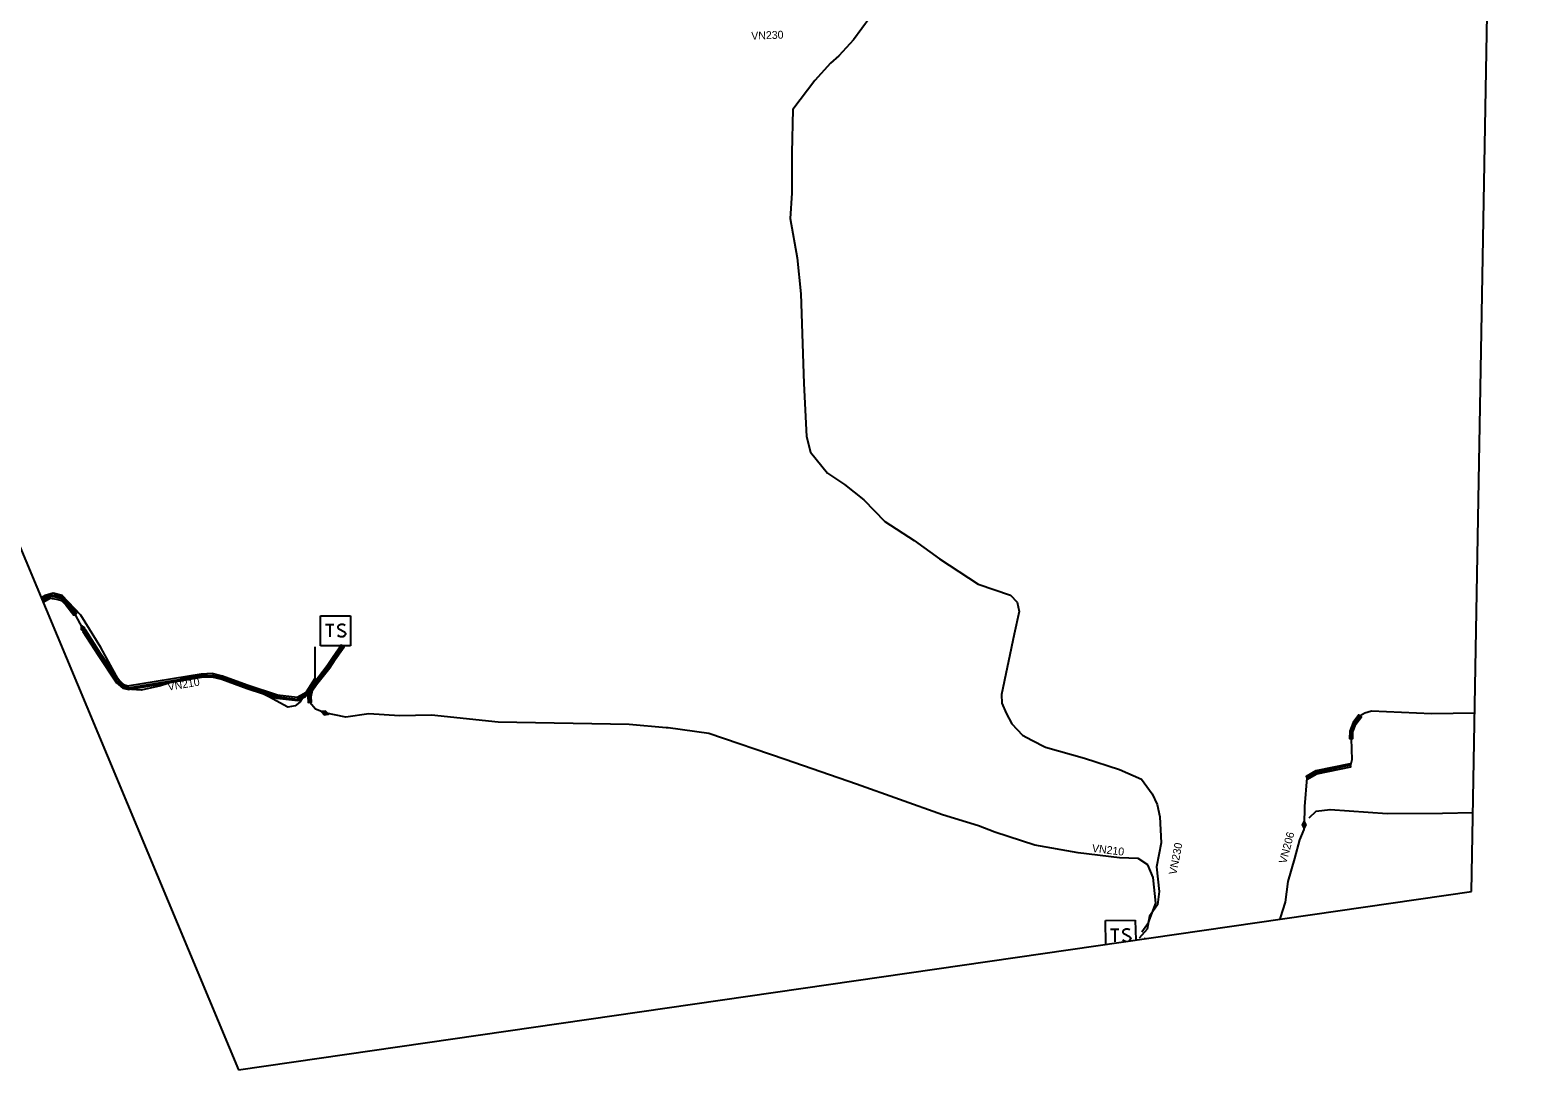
# Model space of a CAD drawing. Extents: x -641829 to -641525, y -1114855 to -1114359.
# Drawn here: x -641715.5 to -641525.3, y -1114854.7 to -1114723.6 of the extents above; entities that cross this region are included whole.
import ezdxf

# ---------------------------------------------------------------- set-up
doc = ezdxf.new("R2010")
doc.units = 0
for name, color, linetype in [('19', 7, 'Continuous'), ('20', 7, 'Continuous'), ('25', 7, 'Continuous'), ('5', 7, 'Continuous'), ('7', 7, 'Continuous'), ('9', 7, 'Continuous'), ('Vrstva 1', 7, 'Continuous')]:
    doc.layers.add(name, color=color, linetype=linetype)

# ---------------------------------------------------------------- blocks, each defined once
blk = doc.blocks.new('VN870')
at = {"layer": '19'}
for points in [[(0, -0.25), (0.5, 0), (0, 0.25), (-0.5, 0), (0, -0.25)], [(0.37, 0), (0, 0.19), (-0.36, 0), (0, -0.19), (0.37, 0)], [(0.24, 0), (0, 0.12), (-0.25, 0), (0, -0.12), (0.24, 0)], [(0.12, 0), (0, 0.06), (-0.13, 0), (0, -0.06), (0.12, 0)]]:
    blk.add_lwpolyline(points, dxfattribs=at)
blk = doc.blocks.new('VN640')
at = {"layer": '25'}
for points in [[(-1.89, 1.89), (1.89, 1.89)], [(-1.89, -1.89), (-1.89, 1.89)], [(-1.26, 0.79), (-0.22, 0.79)], [(-0.73, 0.79), (-0.73, -0.79)], [(1.2, 0.66), (0.94, 0.79), (0.66, 0.79), (0.41, 0.66), (0.28, 0.47), (0.28, 0.41), (0.41, 0.22), (1.13, -0.16), (1.26, -0.32), (1.26, -0.47), (1.13, -0.66), (0.91, -0.79), (0.63, -0.79), (0.5, -0.73), (0.28, -0.6)], [(1.89, 1.89), (1.89, -1.89)], [(1.89, -1.89), (-1.89, -1.89)]]:
    blk.add_lwpolyline(points, dxfattribs=at)

msp = doc.modelspace()

# ---------------------------------------------------------------- linework, layer by layer
at = {"layer": '20'}
for p, q in [((-641713.08, -1114794.84), (-641714.01, -1114795.37)), ((-641714.01, -1114795.37), (-641713.85, -1114795.74)), ((-641713.85, -1114795.74), (-641712.88, -1114795.18)), ((-641712.88, -1114795.18), (-641713.08, -1114794.84))]:
    msp.add_line(p, q, dxfattribs=at)
for points in [[(-641712.95, -1114794.81), (-641713.01, -1114795.21), (-641712.11, -1114795.33), (-641711.51, -1114795.53), (-641710.96, -1114796.05), (-641709.96, -1114797.37), (-641709.64, -1114797.13), (-641710.66, -1114795.79), (-641711.29, -1114795.19), (-641712.01, -1114794.93)], [(-641703.11, -1114806.33), (-641703.59, -1114806.19), (-641704.27, -1114805.61), (-641706.59, -1114802.19), (-641708.49, -1114799.21), (-641708.83, -1114799.43), (-641706.92, -1114802.41), (-641704.57, -1114805.88), (-641703.78, -1114806.55), (-641703.22, -1114806.71)], [(-641676.22, -1114801.12), (-641677.33, -1114802.74), (-641678.01, -1114803.76), (-641679.66, -1114805.88), (-641680.24, -1114806.65), (-641679.92, -1114806.89), (-641679.34, -1114806.12), (-641677.68, -1114804), (-641677, -1114802.96), (-641675.89, -1114801.34)], [(-641680.21, -1114806.62), (-641680.97, -1114807.29), (-641681.8, -1114807.73), (-641684.28, -1114807.44), (-641687.97, -1114806.25), (-641691.2, -1114805.05), (-641692.51, -1114804.73), (-641693.9, -1114804.8), (-641703.2, -1114806.32), (-641703.13, -1114806.72), (-641693.86, -1114805.2), (-641692.55, -1114805.13), (-641691.32, -1114805.43), (-641688.1, -1114806.63), (-641684.37, -1114807.84), (-641681.72, -1114808.14), (-641680.74, -1114807.62), (-641679.94, -1114806.92)], [(-641680.27, -1114806.73), (-641680.45, -1114807.61), (-641680.39, -1114808.38), (-641679.99, -1114808.35), (-641680.04, -1114807.63), (-641679.88, -1114806.81)], [(-641549.02, -1114811.98), (-641549.04, -1114812.93), (-641548.64, -1114812.93), (-641548.62, -1114812.06), (-641548.24, -1114811.09), (-641547.55, -1114810.19), (-641547.87, -1114809.95), (-641548.6, -1114810.89)], [(-641553.3, -1114817.01), (-641554.54, -1114817.7), (-641554.34, -1114818.05), (-641553.16, -1114817.39), (-641548.9, -1114816.5), (-641548.98, -1114816.1)]]:
    msp.add_lwpolyline(points, close=True, dxfattribs=at)
at = {"layer": '25'}
for points in [[(-641579.85, -1114835.89), (-641576.08, -1114835.83)], [(-641579.8, -1114838.88), (-641579.85, -1114835.89)], [(-641579.21, -1114836.98), (-641578.17, -1114836.97)], [(-641578.67, -1114836.97), (-641578.64, -1114838.55)], [(-641576.75, -1114837.07), (-641577, -1114836.95), (-641577.29, -1114836.95), (-641577.53, -1114837.08), (-641577.66, -1114837.27), (-641577.66, -1114837.34), (-641577.53, -1114837.52), (-641576.8, -1114837.89), (-641576.67, -1114838.04), (-641576.66, -1114838.2), (-641576.79, -1114838.39), (-641576.92, -1114838.47)], [(-641576.08, -1114835.83), (-641576.03, -1114838.34)], [(-641577.3, -1114838.52), (-641577.42, -1114838.46), (-641577.64, -1114838.34)]]:
    msp.add_lwpolyline(points, dxfattribs=at)
at = {"layer": '5'}
for points in [[(-641609.52, -1114721.95), (-641611.62, -1114724.81), (-641613.46, -1114726.81), (-641614.54, -1114727.75), (-641616.51, -1114729.93), (-641619.26, -1114733.57), (-641619.4, -1114739.04), (-641619.39, -1114744.13), (-641619.61, -1114747.32), (-641618.74, -1114752.3), (-641618.25, -1114756.85), (-641617.89, -1114768.13), (-641617.56, -1114774.82), (-641617.03, -1114776.78), (-641614.89, -1114779.43), (-641612.74, -1114780.86), (-641610.31, -1114782.8), (-641607.66, -1114785.54), (-641603.96, -1114787.96), (-641600.77, -1114790.25), (-641595.88, -1114793.45), (-641591.83, -1114794.85), (-641590.97, -1114795.73), (-641590.71, -1114796.88), (-641591.34, -1114799.74), (-641592.97, -1114807.37), (-641592.9, -1114808.44), (-641592.36, -1114809.74), (-641591.65, -1114811.05), (-641590.31, -1114812.51), (-641589.13, -1114813.11), (-641587.4, -1114814.03), (-641582.48, -1114815.4), (-641578.09, -1114816.83), (-641575.3, -1114818.05), (-641573.93, -1114819.88), (-641573.32, -1114821.25), (-641573, -1114822.79), (-641572.81, -1114826.07), (-641573.4, -1114829.1), (-641573.08, -1114832.23), (-641573.28, -1114833.89), (-641574.27, -1114835.31), (-641574.6, -1114836.95), (-641575.61, -1114838.1)], [(-641708.82, -1114799.06), (-641709.8, -1114797.25), (-641710.81, -1114795.92), (-641711.4, -1114795.36), (-641712.06, -1114795.13), (-641712.98, -1114795.01), (-641713.93, -1114795.55)], [(-641708.82, -1114799.06), (-641708.66, -1114799.32), (-641706.76, -1114802.3), (-641704.42, -1114805.75), (-641703.69, -1114806.37), (-641703.17, -1114806.52), (-641693.88, -1114805), (-641692.53, -1114804.93), (-641691.26, -1114805.24), (-641688.04, -1114806.44), (-641684.33, -1114807.64), (-641681.76, -1114807.94), (-641680.86, -1114807.46), (-641680.23, -1114806.91), (-641679.77, -1114806.2), (-641679.58, -1114805.94), (-641677.93, -1114803.82), (-641677.25, -1114802.79), (-641676.14, -1114801.17)], [(-641678.31, -1114809.68), (-641679.47, -1114809.21), (-641680.19, -1114808.37), (-641680.25, -1114807.62), (-641680.11, -1114806.91), (-641679.55, -1114806.23), (-641679.42, -1114806.06), (-641677.77, -1114803.94), (-641677.08, -1114802.9), (-641675.97, -1114801.29)], [(-641575.27, -1114837.29), (-641574.41, -1114836.12), (-641573.48, -1114833.67), (-641573.81, -1114830.43), (-641574.48, -1114828.84), (-641575.7, -1114828.06), (-641578.07, -1114827.95), (-641583.29, -1114827.32), (-641588.77, -1114826.38), (-641593.8, -1114824.74), (-641595.84, -1114823.94), (-641600.39, -1114822.53), (-641611.26, -1114818.68), (-641620.24, -1114815.58), (-641629.87, -1114812.27), (-641635.02, -1114811.59), (-641635.27, -1114811.58), (-641639.9, -1114811.15), (-641656.45, -1114810.84), (-641664.85, -1114809.98), (-641668.91, -1114810.05), (-641672.74, -1114809.82), (-641675.65, -1114810.24), (-641678.31, -1114809.68)], [(-641533.26, -1114809.73), (-641538.73, -1114809.8), (-641546.3, -1114809.48), (-641547.14, -1114809.71), (-641547.71, -1114810.07), (-641548.42, -1114810.99), (-641548.82, -1114812.02), (-641548.84, -1114812.93), (-641548.75, -1114815.62), (-641548.94, -1114816.3), (-641553.23, -1114817.2), (-641554.44, -1114817.87), (-641554.73, -1114821.51), (-641554.76, -1114823.79)], [(-641557.88, -1114835.71), (-641557.76, -1114835.54), (-641557.13, -1114833.56), (-641556.79, -1114830.94), (-641555.96, -1114828.06), (-641555.33, -1114825.71), (-641554.78, -1114824.41), (-641554.76, -1114823.79)], [(-641574.82, -1114838.16), (-641574.93, -1114838.13)]]:
    msp.add_lwpolyline(points, dxfattribs=at)
at = {"layer": '9'}
for points in [[(-641679.58, -1114801.37), (-641679.59, -1114805.35), (-641680.94, -1114807.53), (-641681.46, -1114808.32), (-641682.06, -1114808.79), (-641682.99, -1114808.98), (-641685.36, -1114807.66), (-641687.55, -1114806.57), (-641691.62, -1114805.27), (-641693.31, -1114804.91), (-641695.22, -1114805.04), (-641699.03, -1114806.29), (-641701.49, -1114806.82), (-641702.64, -1114806.73), (-641703.71, -1114806.24), (-641704.36, -1114805.43), (-641706.56, -1114801.44), (-641709.09, -1114797.38), (-641711.42, -1114794.88), (-641712.56, -1114794.58), (-641713.6, -1114794.86), (-641714.1, -1114795.16)], [(-641554.15, -1114822.93), (-641553.25, -1114822.1), (-641551.49, -1114821.87), (-641544.3, -1114822.38), (-641537.31, -1114822.32), (-641533.48, -1114822.24)]]:
    msp.add_lwpolyline(points, dxfattribs=at)
at = {"layer": 'Vrstva 1'}
for p, q in [((-641533.66, -1114832.21), (-641525.3, -1114362.64)), ((-641812.64, -1114559.36), (-641689.21, -1114854.71)), ((-641689.21, -1114854.71), (-641533.66, -1114832.21))]:
    msp.add_line(p, q, dxfattribs=at)

# ---------------------------------------------------------------- block references
at = {"layer": '19'}
for p, rotation in [((-641708.82, -1114799.06), 117), ((-641678.31, -1114809.68), 158), ((-641554.76, -1114823.79), 90)]:
    msp.add_blockref('VN870', p, dxfattribs=dict(at, rotation=rotation))
at = {"layer": '25'}
msp.add_blockref('VN640', (-641676.95, -1114799.32), dxfattribs=at)

# ---------------------------------------------------------------- texts
at = {"layer": '7'}
for s, rotation, p in [('VN230', 2.1172, (-641624.5, -1114724.78)), ('VN210', 9.2922, (-641698.05, -1114806.89)), ('VN206', 74.9473, (-641557.04, -1114828.78)), ('VN210', 353.1603, (-641581.58, -1114827.22)), ('VN230', 79.0794, (-641570.89, -1114830.16))]:
    msp.add_text(s, height=0.994, rotation=rotation, dxfattribs=at).set_placement(p)

doc.saveas('drawing.dxf')
